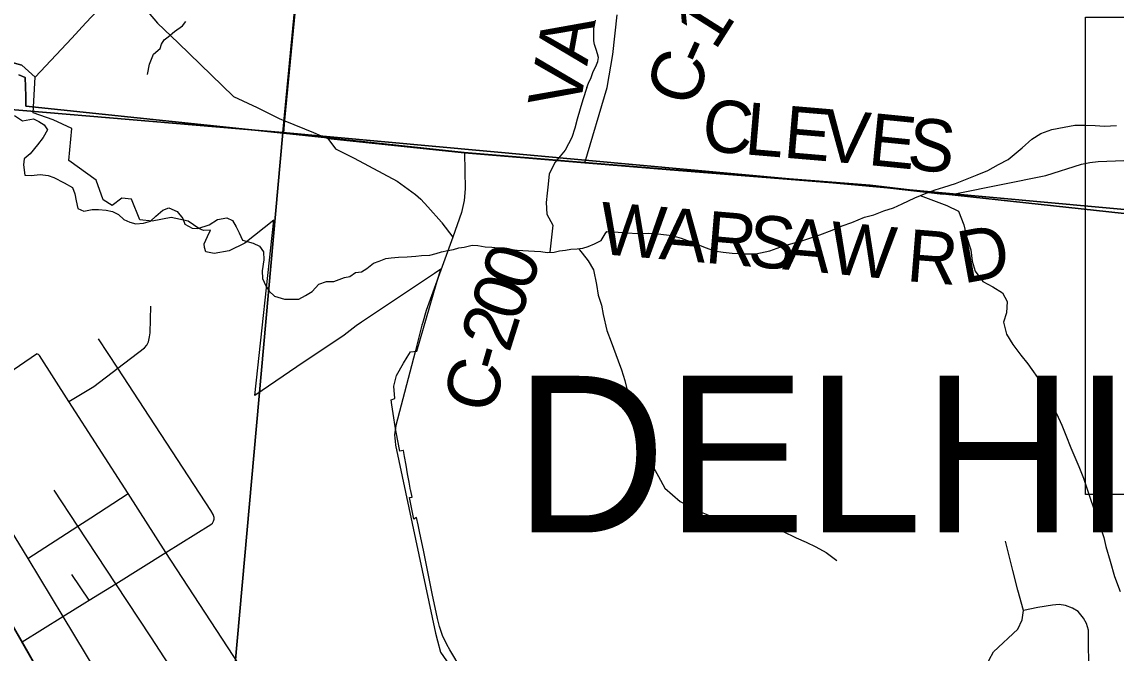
# Model space of a CAD drawing. Extents: x 0 to 34, y 0 to 22.
# Drawn here: x 3.46 to 4.65, y 17.149 to 17.836 of the extents above; entities that cross this region are included whole.
import ezdxf

# ---------------------------------------------------------------- set-up
doc = ezdxf.new("R2010")
doc.units = 0
for name, color, linetype in [('GM_X_City_Street', 7, 'Continuous'), ('GM_X_Corporation', 7, 'Continuous'), ('GM_X_County_Road', 7, 'Continuous'), ('GM_X_County_Road_Text', 7, 'Continuous'), ('GM_X_Minor_River', 7, 'Continuous'), ('GM_X_Rail_Line', 7, 'Continuous'), ('GM_X_Township_Road', 7, 'Continuous'), ('GM_X_Township_Text', 7, 'Continuous'), ('SH_Masking', 7, 'Continuous'), ('SH_Text', 7, 'Continuous')]:
    doc.layers.add(name, color=color, linetype=linetype)

msp = doc.modelspace()

# ---------------------------------------------------------------- linework, layer by layer
at = {"layer": 'GM_X_City_Street'}
msp.add_line((3.533, 17.2067), (3.5141, 17.2345), dxfattribs=at)
for points in [[(3.5106, 17.423), (3.538, 17.4391), (3.5639, 17.459), (3.593, 17.4813), (3.5956, 17.4841), (3.5973, 17.4878), (3.5986, 17.4931), (3.5992, 17.4975), (3.5998, 17.5264)], [(3.6688, 17.2965), (3.6685, 17.2978), (3.6675, 17.3), (3.6651, 17.3042), (3.5926, 17.4152), (3.5639, 17.459), (3.5431, 17.491)], [(3.3718, 17.4041), (3.4124, 17.4317), (3.4198, 17.4367), (3.4757, 17.4747)], [(3.9415, 16.771), (3.8933, 16.8418), (3.8772, 16.8653), (3.8669, 16.8804), (3.8199, 16.9493), (3.7756, 17.0143), (3.7168, 17.1044), (3.6955, 17.1369), (3.6162, 17.2585), (3.5751, 17.3226), (3.5106, 17.423), (3.4787, 17.4728), (3.4776, 17.474), (3.4757, 17.4747)], [(3.684, 17.0404), (3.6667, 17.0663), (3.6417, 17.1037), (3.6148, 17.1441), (3.5998, 17.1666), (3.5617, 17.2245), (3.5205, 17.2872), (3.4947, 17.3265)], [(3.466, 17.2519), (3.5205, 17.2872), (3.5345, 17.2963), (3.5751, 17.3226)], [(3.4599, 17.1612), (3.5042, 17.1888), (3.5281, 17.2036), (3.533, 17.2067), (3.5617, 17.2245), (3.6162, 17.2585), (3.6653, 17.289), (3.6669, 17.2905), (3.6681, 17.2925), (3.6687, 17.2947), (3.6688, 17.2965)], [(3.4432, 17.285), (3.4453, 17.2847), (3.4469, 17.2834), (3.466, 17.2519), (3.5042, 17.1888), (3.5412, 17.1277), (3.5791, 17.0651), (3.5845, 17.0563), (3.6148, 17.0061), (3.6559, 16.9382), (3.6953, 16.8731), (3.7344, 16.8086)]]:
    msp.add_lwpolyline(points, dxfattribs=at)
at = {"layer": 'GM_X_Corporation'}
for points in [[(3.4565, 17.7784), (3.4633, 17.7753), (3.4638, 17.7552), (3.4639, 17.7441), (3.744, 17.7149), (3.7454, 17.7286), (3.8023, 18.3182), (3.8126, 18.3974), (3.8234, 18.553), (3.8667, 18.9339), (3.918, 19.4442), (3.9936, 20.1954), (4.0006, 20.2658), (4.0111, 20.3696), (4.0645, 20.9), (2.1, 20.9)], [(3.8023, 18.3182), (3.7454, 17.7286), (3.744, 17.7149), (3.7921, 17.7096), (3.9407, 17.6938), (4.0716, 17.683), (4.1644, 17.6754), (4.3821, 17.6581), (4.4612, 17.6488), (4.8521, 17.6062), (5.4373, 17.5132), (5.7944, 17.4564), (6.1906, 17.4068), (6.2062, 17.4054), (6.4189, 17.3858), (6.5022, 17.378), (6.7303, 17.3529), (6.8401, 17.3411), (6.9337, 17.3322)], [(3.4452, 17.7926), (3.4597, 17.7888), (3.4742, 17.7758), (3.514, 17.8182), (3.5292, 17.8347), (3.5691, 17.8771)], [(2.8521, 17.7909), (3.7435, 17.7155), (3.6418, 16.5845)], [(3.9385, 17.1301), (3.925, 17.1527), (3.9219, 17.1583), (3.9171, 17.1683), (3.9138, 17.1782), (3.9115, 17.1866), (3.9059, 17.214), (3.8965, 17.2609), (3.8925, 17.2794), (3.8905, 17.2886), (3.8888, 17.2967), (3.886, 17.2949), (3.881, 17.3183), (3.884, 17.3189), (3.8825, 17.3256), (3.8824, 17.3262), (3.8808, 17.335), (3.8791, 17.3443), (3.8774, 17.3536), (3.8757, 17.3629), (3.8746, 17.3695), (3.8743, 17.3694), (3.8706, 17.3687), (3.8665, 17.3896), (3.8652, 17.3978), (3.8641, 17.4049), (3.8618, 17.4193), (3.8614, 17.4247), (3.8651, 17.426), (3.8641, 17.4395), (3.8671, 17.4511), (3.8748, 17.4647), (3.8788, 17.471), (3.8823, 17.4767), (3.889, 17.4777), (3.9102, 17.5501), (3.9152, 17.5667), (3.9084, 17.5622), (3.9074, 17.5615), (3.829, 17.5091), (3.8233, 17.5052), (3.8102, 17.4951), (3.7588, 17.4604), (3.713, 17.4295), (3.7338, 17.6202), (3.7022, 17.5951), (3.685, 17.5869), (3.6689, 17.5838), (3.6598, 17.5857), (3.6582, 17.5903), (3.658, 17.5942), (3.6615, 17.6022), (3.6646, 17.6091), (3.6573, 17.6087), (3.6519, 17.6109), (3.6405, 17.6191), (3.6219, 17.6231), (3.6012, 17.6189), (3.5881, 17.6204), (3.5789, 17.6428), (3.5685, 17.6441), (3.5579, 17.636), (3.548, 17.6422), (3.5404, 17.6636), (3.5106, 17.6852), (3.514, 17.72), (3.4938, 17.7291), (3.4719, 17.7368), (3.4742, 17.7758), (3.4597, 17.7888), (3.4452, 17.7926)], [(6.9337, 17.3322), (6.8401, 17.3411), (6.7303, 17.3529), (6.5022, 17.378), (6.4189, 17.3858), (6.2062, 17.4054), (6.1906, 17.4068), (5.7944, 17.4564), (5.4373, 17.5132), (4.8521, 17.6062), (4.4612, 17.6488), (4.3821, 17.6581), (4.1644, 17.6754), (4.0716, 17.683), (3.9407, 17.6938), (3.7921, 17.7096), (3.744, 17.7149), (3.4639, 17.7441), (3.4638, 17.7552), (3.4633, 17.7753), (3.4565, 17.7784)]]:
    msp.add_lwpolyline(points, dxfattribs=at)
for points in [[(3.8378, 18.696), (3.7435, 17.7155), (2.8521, 17.7909), (2.8154, 17.7918), (2.8147, 17.7929), (2.7902, 17.8358), (2.7645, 17.8808), (2.7638, 17.8821), (2.7489, 17.9091), (2.8429, 18.8167)], [(4.8473, 18.5791), (4.7377, 17.6243), (3.7435, 17.7155), (3.8378, 18.696)], [(4.7377, 17.6243), (4.6148, 16.5127), (3.671, 16.5519), (3.6538, 16.5645), (3.6462, 16.5775), (3.6418, 16.5845), (3.7435, 17.7155)]]:
    msp.add_lwpolyline(points, close=True, dxfattribs=at)
at = {"layer": 'GM_X_County_Road'}
for points in [[(3.551, 17.8973), (3.5807, 17.8659), (3.6073, 17.8343), (3.6297, 17.8131), (3.6897, 17.7545), (3.7156, 17.7426), (3.7393, 17.7307), (3.7418, 17.7296), (3.7456, 17.7281), (3.7766, 17.7155), (3.7825, 17.7131)], [(4.0718, 17.6825), (4.096, 17.7644), (4.1021, 17.8003), (4.1069, 17.8434)], [(3.7825, 17.7131), (3.7924, 17.7091), (3.9409, 17.6933)], [(3.7924, 17.7091), (3.8007, 17.6979), (3.821, 17.6876), (3.8678, 17.6627), (3.8876, 17.6482), (3.8936, 17.6431), (3.901, 17.6346), (3.9158, 17.618)], [(3.9409, 17.6933), (3.9416, 17.6542), (3.9406, 17.6414), (3.9376, 17.6285), (3.9283, 17.6016), (3.8993, 17.522), (3.8953, 17.5077), (3.895, 17.5068)], [(3.9409, 17.6933), (4.0718, 17.6825), (4.1647, 17.6748), (4.3824, 17.6576), (4.4168, 17.6535)], [(4.4168, 17.6535), (4.4614, 17.6483), (4.4758, 17.6493), (4.573, 17.6686), (4.6118, 17.6811), (4.621, 17.683), (4.6299, 17.6841), (4.6769, 17.6859), (4.7272, 17.6849), (4.7442, 17.6849), (4.7505, 17.6841), (4.7568, 17.6836), (4.7631, 17.6828), (4.7784, 17.6791), (4.7885, 17.6731), (4.8014, 17.6625), (4.8162, 17.6498), (4.8353, 17.6318), (4.8442, 17.6221), (4.8523, 17.6057), (4.8596, 17.5869), (4.8662, 17.5688), (4.8895, 17.4998), (4.8925, 17.4918)], [(3.9158, 17.618), (3.9165, 17.6172), (3.9283, 17.6016)], [(3.895, 17.5068), (3.8947, 17.5058), (3.8873, 17.4768), (3.8662, 17.3968), (3.8648, 17.3866), (3.8652, 17.3828), (3.8656, 17.3796)], [(3.8656, 17.3796), (3.8661, 17.3752), (3.9094, 17.1706), (3.9115, 17.1626), (3.915, 17.15), (3.9363, 17.1193), (3.9407, 17.1131), (3.9477, 17.1015), (3.9526, 17.0855), (3.9596, 17.0599), (3.963, 17.0415), (3.9778, 16.9592), (3.9875, 16.9057), (3.9912, 16.8851)], [(4.6183, 16.773), (4.5705, 16.8235), (4.5673, 16.8314), (4.5659, 16.8396), (4.5647, 16.8532), (4.5625, 16.8732), (4.5587, 16.8838), (4.5533, 16.894), (4.5253, 16.9283), (4.519, 16.9389), (4.5152, 16.9519), (4.4903, 17.0548), (4.4879, 17.0674), (4.4881, 17.0736), (4.5065, 17.1263), (4.5116, 17.1417), (4.5162, 17.1504), (4.5427, 17.1753), (4.5473, 17.1852), (4.549, 17.1954), (4.5427, 17.2176), (4.5372, 17.2388), (4.5294, 17.2707)], [(3.4403, 17.1954), (3.4599, 17.1612), (3.4955, 17.0991), (3.5317, 17.0358), (3.5663, 16.9763), (3.6066, 16.9069), (3.6432, 16.8438), (3.6835, 16.7746), (3.6969, 16.7516), (3.713, 16.7258), (3.7609, 16.6611), (3.7657, 16.655), (3.7823, 16.6344), (3.804, 16.6055), (3.846, 16.5432), (3.887, 16.4854), (3.8904, 16.4808), (3.9025, 16.4638), (3.9229, 16.4395), (3.9444, 16.4189), (3.95, 16.4142), (3.9523, 16.4123)]]:
    msp.add_lwpolyline(points, dxfattribs=at)
at = {"layer": 'GM_X_Minor_River'}
for points in [[(4.0741, 17.7644), (4.0758, 17.7693), (4.0787, 17.7753), (4.0808, 17.782), (4.0837, 17.7872), (4.0861, 17.7929), (4.0866, 17.797), (4.0857, 17.8012), (4.0843, 17.8059), (4.0822, 17.8112), (4.0816, 17.8154), (4.0815, 17.8234), (4.0817, 17.8287), (4.0835, 17.8378)], [(3.5963, 17.7786), (3.5986, 17.7899), (3.6027, 17.8008), (3.6102, 17.807), (3.6115, 17.8115), (3.6143, 17.8163), (3.6186, 17.8196), (3.6256, 17.8255), (3.6342, 17.8316), (3.6381, 17.8361)], [(4.0741, 17.7644), (4.0698, 17.7511), (4.0666, 17.7413), (4.0636, 17.73), (4.0611, 17.7202), (4.0578, 17.71), (4.0506, 17.6962), (4.0397, 17.6831), (4.0329, 17.6704), (4.0318, 17.6594), (4.0308, 17.6496), (4.0298, 17.6393), (4.0306, 17.6268), (4.0372, 17.6148), (4.0338, 17.5852)], [(3.4516, 17.7341), (3.4603, 17.7283), (3.4722, 17.7303), (3.4782, 17.7276), (3.4839, 17.724), (3.4876, 17.7183), (3.4829, 17.71), (3.4766, 17.7021), (3.4688, 17.6924), (3.4622, 17.6868), (3.4613, 17.6803), (3.4627, 17.6689), (3.4699, 17.6688), (3.4795, 17.6698), (3.4882, 17.6688), (3.4943, 17.6665), (3.5057, 17.6609), (3.5147, 17.6555), (3.5173, 17.6489), (3.5187, 17.6413), (3.5204, 17.6329), (3.5269, 17.6298), (3.5361, 17.6319), (3.5429, 17.6318), (3.5513, 17.6309), (3.5582, 17.6296), (3.5646, 17.6264), (3.5706, 17.621), (3.577, 17.6179), (3.5835, 17.6162), (3.5919, 17.6168), (3.5996, 17.619), (3.6054, 17.6246), (3.6128, 17.6309), (3.6193, 17.6335), (3.6284, 17.6295), (3.6348, 17.6218), (3.637, 17.6157), (3.6449, 17.6113), (3.651, 17.6112), (3.6633, 17.6152), (3.6722, 17.6207), (3.6825, 17.6228), (3.6886, 17.6197), (3.6927, 17.6128), (3.696, 17.6062), (3.6996, 17.5982), (3.711, 17.595), (3.7182, 17.5918), (3.7223, 17.5856), (3.7229, 17.5769), (3.7208, 17.5651), (3.7214, 17.5568), (3.7251, 17.5487), (3.7284, 17.543), (3.7344, 17.5375), (3.7454, 17.5343), (3.7527, 17.5342), (3.7607, 17.534), (3.768, 17.5381), (3.7754, 17.5425), (3.7824, 17.5504), (3.7908, 17.5533), (3.7989, 17.5535), (3.8104, 17.5578), (3.8162, 17.5589), (3.8223, 17.563), (3.8288, 17.564), (3.8346, 17.5677), (3.842, 17.5733), (3.8481, 17.5754), (3.8555, 17.5783), (3.8612, 17.579), (3.8692, 17.58), (3.8788, 17.5802), (3.888, 17.5808), (3.8941, 17.5815), (3.9033, 17.5821), (3.9102, 17.5838), (3.9159, 17.5856), (3.9228, 17.587), (3.9289, 17.5881), (3.9347, 17.5899), (3.9405, 17.5909), (3.9493, 17.593), (3.9554, 17.5925), (3.9634, 17.5912), (3.9706, 17.5907), (3.9771, 17.5899), (3.9843, 17.5894), (3.9981, 17.5876), (4.0045, 17.5871), (4.0106, 17.5866), (4.0171, 17.5865), (4.024, 17.586), (4.0308, 17.5851), (4.0385, 17.5854), (4.0442, 17.5868)], [(4.0956, 17.6077), (4.1038, 17.6075), (4.1166, 17.6064), (4.1303, 17.6057), (4.1409, 17.6058), (4.1515, 17.6052), (4.1663, 17.6033), (4.1765, 17.6007), (4.1892, 17.5959), (4.2009, 17.591), (4.2125, 17.5869), (4.2224, 17.5852), (4.2322, 17.5841), (4.2451, 17.5834), (4.2576, 17.5835), (4.2729, 17.5869), (4.2848, 17.5912), (4.2958, 17.5943), (4.3077, 17.5978), (4.3176, 17.601), (4.3272, 17.6042), (4.3406, 17.6092), (4.3517, 17.6138), (4.3621, 17.6174), (4.3759, 17.6235), (4.3862, 17.6259), (4.3969, 17.6302), (4.4073, 17.6337), (4.4169, 17.638), (4.4307, 17.6445), (4.443, 17.6495), (4.4526, 17.6531), (4.4621, 17.6559), (4.4748, 17.6601), (4.4874, 17.6651), (4.4985, 17.6694), (4.51, 17.6741), (4.5216, 17.6806), (4.532, 17.686), (4.5475, 17.6989), (4.5579, 17.7082), (4.5676, 17.7144), (4.5798, 17.7186), (4.5932, 17.7213), (4.6046, 17.7233), (4.616, 17.7234), (4.6266, 17.7232), (4.6369, 17.7225), (4.6498, 17.723)], [(4.4365, 17.6469), (4.4654, 17.6361), (4.4782, 17.63), (4.4839, 17.6151), (4.4869, 17.6025), (4.4915, 17.5879), (4.4931, 17.5754), (4.4962, 17.5646), (4.5047, 17.5534), (4.5155, 17.5475), (4.526, 17.5411), (4.5311, 17.5315), (4.5304, 17.5194), (4.5271, 17.5092), (4.5305, 17.4962), (4.5371, 17.485), (4.5459, 17.4734), (4.5536, 17.4637), (4.5683, 17.4428), (4.5741, 17.4332), (4.5795, 17.4201), (4.5849, 17.4098), (4.5907, 17.3971), (4.5949, 17.3863), (4.6003, 17.3725), (4.6046, 17.3622), (4.6089, 17.3522), (4.6142, 17.3395), (4.6178, 17.3284), (4.622, 17.3154), (4.6319, 17.2878), (4.6361, 17.2748), (4.6385, 17.2649), (4.6431, 17.2492), (4.6479, 17.2323), (4.654, 17.2162)], [(4.0442, 17.5868), (4.0507, 17.5874), (4.0565, 17.5885), (4.0634, 17.5891), (4.0695, 17.5897), (4.0753, 17.5915), (4.0822, 17.5945), (4.0895, 17.5981), (4.0938, 17.6053), (4.0956, 17.6077)], [(4.0648, 17.5892), (4.0753, 17.5759), (4.0811, 17.5659), (4.0845, 17.5502), (4.0864, 17.5384), (4.09, 17.5277), (4.0916, 17.5174), (4.0957, 17.5002), (4.1003, 17.4876), (4.1082, 17.4672), (4.1117, 17.4573), (4.1152, 17.4458), (4.118, 17.4351), (4.1207, 17.4232), (4.1252, 17.4068), (4.1291, 17.3964), (4.1326, 17.385), (4.1383, 17.3704), (4.1444, 17.3551), (4.152, 17.3412), (4.1589, 17.3285), (4.1756, 17.314), (4.1925, 17.3049), (4.2097, 17.2976), (4.2278, 17.2922), (4.2399, 17.2896), (4.2501, 17.289), (4.2619, 17.2879), (4.2721, 17.2865), (4.2868, 17.2816), (4.3018, 17.2744), (4.3126, 17.2696), (4.3231, 17.2648), (4.3344, 17.2584), (4.3459, 17.2498)]]:
    msp.add_lwpolyline(points, dxfattribs=at)
at = {"layer": 'GM_X_Rail_Line'}
msp.add_lwpolyline([(3.4206, 17.2288), (3.4993, 17.0909), (3.6906, 16.7811), (3.7282, 16.7075), (3.7776, 16.6456), (3.8431, 16.5595), (3.8629, 16.5219), (3.926, 16.4427), (4.06, 16.3478), (4.1978, 16.275), (4.2934, 16.2188), (4.3976, 16.1705), (4.4935, 16.127), (4.6314, 16.1011), (4.6907, 16.0865)], dxfattribs=at)
at = {"layer": 'GM_X_Township_Road'}
msp.add_lwpolyline([(4.616, 17.1089), (4.6197, 17.1233), (4.6194, 17.1739), (4.6174, 17.1813), (4.6142, 17.187), (4.6084, 17.1944), (4.602, 17.198), (4.5946, 17.2008), (4.5878, 17.2021), (4.5804, 17.2014), (4.5646, 17.1987), (4.549, 17.1954)], dxfattribs=at)
at = {"layer": 'SH_Masking'}
msp.add_lwpolyline([(4.6164, 17.841), (6.3738, 17.841), (6.3738, 17.3215), (4.6164, 17.3215)], close=True, dxfattribs=at)
at = {"layer": 'SH_Text'}
msp.add_lwpolyline([(4.6164, 17.841), (6.3738, 17.841), (6.3738, 17.3215), (4.6164, 17.3215)], close=True, dxfattribs=at)

# ---------------------------------------------------------------- texts
at = {"layer": 'GM_X_County_Road_Text'}
for s, rotation, p in [('1', 57.6476, (4.2135, 17.8036)), ('A', 79.8418, (4.0743, 17.7874)), ('-', 65.7274, (4.2049, 17.7842)), ('C', 72.5231, (4.1915, 17.7414)), ('V', 79.9972, (4.0656, 17.7382)), ('C', 355.1506, (4.1979, 17.6958)), ('L', 355.1517, (4.2444, 17.6919)), ('E', 355.1515, (4.2867, 17.6883)), ('V', 354.9135, (4.329, 17.6847)), ('E', 354.3036, (4.3787, 17.6803)), ('S', 353.8899, (4.4209, 17.6761)), ('W', 355.2095, (4.0861, 17.5835)), ('A', 355.2078, (4.1517, 17.578)), ('R', 355.2074, (4.2015, 17.5738)), ('S', 355.1907, (4.248, 17.5699)), ('A', 355.0762, (4.2862, 17.5667)), ('W', 354.4942, (4.3359, 17.5624)), ('D', 10.3848, (4.4833, 17.551)), ('R', 355.3878, (4.4206, 17.5539)), ('0', 70.4941, (4.0114, 17.5406)), ('0', 71.0018, (4, 17.5077)), ('2', 72.4731, (3.9896, 17.4747)), ('-', 73.8712, (3.9832, 17.4526)), ('C', 75.6192, (3.9718, 17.4078))]:
    msp.add_text(s, height=0.0568, rotation=rotation, dxfattribs=at).set_placement(p)
at = {"layer": 'GM_X_Township_Text'}
msp.add_text('DELHI', height=0.17045, rotation=0, dxfattribs=at).set_placement((3.9954, 17.2803))

doc.saveas('drawing.dxf')
